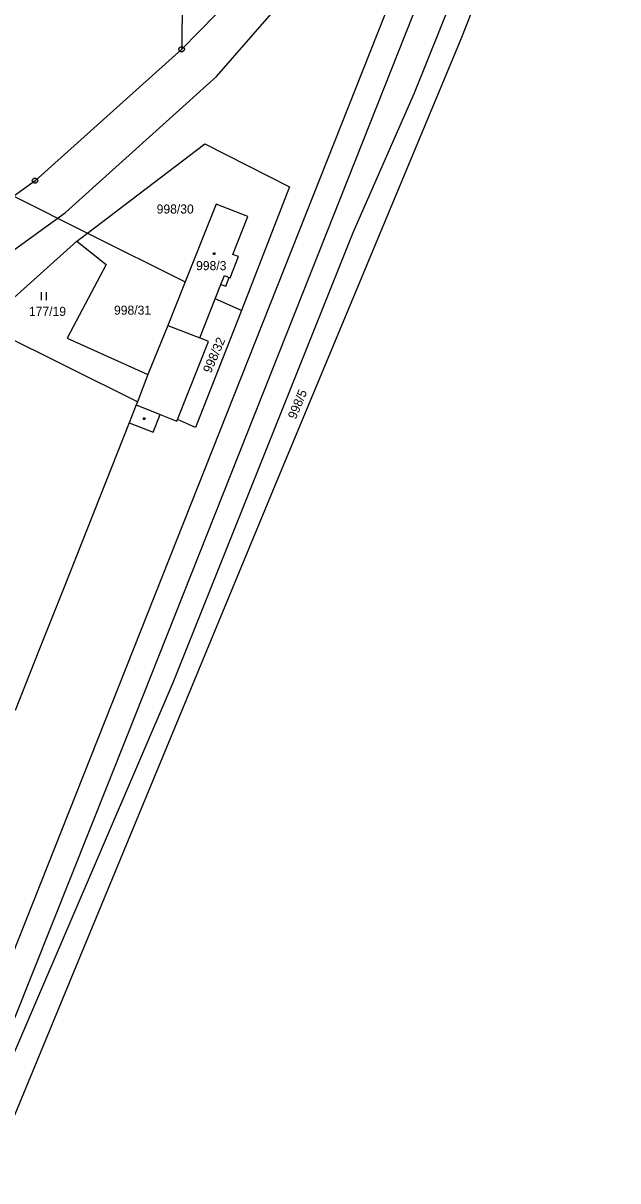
# Model space of a CAD drawing. Extents: x -755359 to -754474, y -1162585 to -1161655.
# Drawn here: x -754898.3 to -754786.7, y -1162361.4 to -1162144.3 of the extents above; entities that cross this region are included whole.
import ezdxf

# ---------------------------------------------------------------- set-up
doc = ezdxf.new("R2010")
doc.units = 0
for name, color, linetype in [('Vrstva 1', 7, 'Continuous'), ('Vrstva 11', 7, 'Continuous'), ('Vrstva 12', 7, 'Continuous'), ('Vrstva 2', 7, 'Continuous'), ('Vrstva 3', 7, 'Continuous'), ('Vrstva 4', 7, 'Continuous'), ('Vrstva 5', 7, 'Continuous'), ('Vrstva 6', 7, 'Continuous'), ('Vrstva 8', 7, 'Continuous')]:
    doc.layers.add(name, color=color, linetype=linetype)

msp = doc.modelspace()

# ---------------------------------------------------------------- linework, layer by layer
at = {"layer": 'Vrstva 1'}
for p, q in [((-754824.89, -1162157.4), (-754808.97, -1162117.64)), ((-754868.42, -1162135.23), (-754868.56, -1162149.23)), ((-754811.54, -1162135.54), (-754816.22, -1162147.35)), ((-754862.16, -1162142.69), (-754868.56, -1162149.23)), ((-754868.56, -1162149.23), (-754896.07, -1162173.88)), ((-754816.22, -1162147.35), (-754851.45, -1162231.96)), ((-754836.4, -1162183.6), (-754824.89, -1162157.4)), ((-754886.23, -1162183.69), (-754864.19, -1162166.97)), ((-754864.19, -1162166.97), (-754848.34, -1162175.05)), ((-754896.07, -1162173.88), (-754900.06, -1162176.77)), ((-754848.34, -1162175.05), (-754857.37, -1162198.21)), ((-754900.06, -1162176.77), (-754886.23, -1162183.69)), ((-754862.1, -1162178.26), (-754867.91, -1162192.86)), ((-754856.15, -1162180.61), (-754862.1, -1162178.26)), ((-754858.96, -1162187.7), (-754856.15, -1162180.61)), ((-754888.26, -1162185.23), (-754886.23, -1162183.69)), ((-754886.23, -1162183.69), (-754867.91, -1162192.86)), ((-754870.17, -1162267.96), (-754836.4, -1162183.6)), ((-754888.26, -1162185.23), (-754905.78, -1162201)), ((-754888.26, -1162185.23), (-754882.73, -1162189.61)), ((-754859.46, -1162192.12), (-754857.88, -1162188.11)), ((-754857.88, -1162188.11), (-754858.96, -1162187.7)), ((-754882.73, -1162189.61), (-754890.05, -1162203.42)), ((-754860.31, -1162193.68), (-754859.66, -1162192.04)), ((-754859.66, -1162192.04), (-754859.46, -1162192.12)), ((-754867.91, -1162192.86), (-754871.15, -1162201.02)), ((-754862.27, -1162196.01), (-754861.2, -1162193.33)), ((-754861.2, -1162193.33), (-754860.31, -1162193.68)), ((-754865.18, -1162203.36), (-754862.27, -1162196.01)), ((-754857.37, -1162198.21), (-754862.27, -1162196.01)), ((-754857.37, -1162198.21), (-754865.94, -1162220.19)), ((-754876.85, -1162215.37), (-754905.78, -1162201)), ((-754871.15, -1162201.02), (-754874.91, -1162210.24)), ((-754890.05, -1162203.42), (-754874.91, -1162210.24)), ((-754863.54, -1162204.02), (-754865.18, -1162203.36)), ((-754869.36, -1162218.68), (-754863.54, -1162204.02)), ((-754874.91, -1162210.24), (-754876.85, -1162215.37)), ((-754877.09, -1162215.93), (-754878.41, -1162219.27)), ((-754876.85, -1162215.37), (-754877.09, -1162215.93)), ((-754873.93, -1162221.05), (-754872.61, -1162217.71)), ((-754872.61, -1162217.71), (-754869.47, -1162218.96)), ((-754869.47, -1162218.96), (-754869.36, -1162218.68)), ((-754865.94, -1162220.19), (-754869.36, -1162218.68)), ((-754878.41, -1162219.27), (-754890.63, -1162250.1)), ((-754878.41, -1162219.27), (-754873.93, -1162221.05)), ((-754851.45, -1162231.96), (-754887.61, -1162319.28)), ((-754890.63, -1162250.1), (-754895.21, -1162261.65)), ((-754895.21, -1162261.65), (-754899.8, -1162273.21)), ((-754930.02, -1162407.36), (-754870.17, -1162267.96)), ((-754887.61, -1162319.28), (-754904.19, -1162359.38))]:
    msp.add_line(p, q, dxfattribs=at)
at = {"layer": 'Vrstva 11'}
for p, q in [((-754811.54, -1162135.54), (-754816.22, -1162147.35)), ((-754816.22, -1162147.35), (-754851.45, -1162231.96)), ((-754851.45, -1162231.96), (-754887.61, -1162319.28)), ((-754887.61, -1162319.28), (-754904.19, -1162359.38))]:
    msp.add_line(p, q, dxfattribs=at)
at = {"layer": 'Vrstva 12'}
for p, q in [((-754862.1, -1162178.26), (-754867.91, -1162192.86)), ((-754856.15, -1162180.61), (-754862.1, -1162178.26)), ((-754858.96, -1162187.7), (-754856.15, -1162180.61)), ((-754859.46, -1162192.12), (-754857.88, -1162188.11)), ((-754857.88, -1162188.11), (-754858.96, -1162187.7)), ((-754861.2, -1162193.33), (-754860.55, -1162191.69)), ((-754860.55, -1162191.69), (-754859.66, -1162192.04)), ((-754859.66, -1162192.04), (-754859.46, -1162192.12)), ((-754867.91, -1162192.86), (-754871.15, -1162201.02)), ((-754862.27, -1162196.01), (-754861.2, -1162193.33)), ((-754865.18, -1162203.36), (-754862.27, -1162196.01)), ((-754871.15, -1162201.02), (-754865.18, -1162203.36))]:
    msp.add_line(p, q, dxfattribs=at)
at = {"layer": 'Vrstva 3'}
for p, q in [((-754894.89, -1162194.76), (-754894.89, -1162196.26)), ((-754893.89, -1162196.26), (-754893.89, -1162194.76))]:
    msp.add_line(p, q, dxfattribs=at)
at = {"layer": 'Vrstva 4'}
for p, q in [((-754861.2, -1162193.33), (-754860.55, -1162191.69)), ((-754860.55, -1162191.69), (-754859.66, -1162192.04)), ((-754871.15, -1162201.02), (-754865.18, -1162203.36)), ((-754877.09, -1162215.93), (-754872.61, -1162217.71))]:
    msp.add_line(p, q, dxfattribs=at)
at = {"layer": 'Vrstva 5'}
for points in [[(-754862.4, -1162187.42), (-754862.31, -1162187.57), (-754862.4, -1162187.72), (-754862.58, -1162187.72), (-754862.67, -1162187.57), (-754862.58, -1162187.42)], [(-754875.49, -1162218.34), (-754875.4, -1162218.49), (-754875.49, -1162218.64), (-754875.67, -1162218.64), (-754875.76, -1162218.49), (-754875.67, -1162218.34)]]:
    msp.add_lwpolyline(points, close=True, dxfattribs=at)
at = {"layer": 'Vrstva 6'}
for p, q in [((-755000.46, -1162571.42), (-754786.74, -1162032.64)), ((-754811.99, -1162109.48), (-754841.46, -1162183.87)), ((-754862.02, -1162154.33), (-754839.32, -1162128.13)), ((-754890.36, -1162179.87), (-754862.02, -1162154.33)), ((-754910.99, -1162194.73), (-754890.36, -1162179.87)), ((-754841.46, -1162183.87), (-754878.79, -1162277.91)), ((-754878.79, -1162277.91), (-754899.91, -1162330.95))]:
    msp.add_line(p, q, dxfattribs=at)
at = {"layer": 'Vrstva 8'}
for p, q in [((-754868.68, -1162149.23), (-754868.44, -1162149.23)), ((-754896.19, -1162173.88), (-754895.95, -1162173.88))]:
    msp.add_line(p, q, dxfattribs=at)
for points in [[(-754868.41, -1162148.75), (-754868.16, -1162148.93), (-754868.06, -1162149.22), (-754868.16, -1162149.51), (-754868.41, -1162149.69), (-754868.72, -1162149.69), (-754868.97, -1162149.51), (-754869.07, -1162149.22), (-754868.97, -1162148.93), (-754868.72, -1162148.75)], [(-754895.92, -1162173.4), (-754895.67, -1162173.58), (-754895.57, -1162173.87), (-754895.67, -1162174.16), (-754895.92, -1162174.34), (-754896.23, -1162174.34), (-754896.48, -1162174.16), (-754896.58, -1162173.87), (-754896.48, -1162173.58), (-754896.23, -1162173.4)]]:
    msp.add_lwpolyline(points, close=True, dxfattribs=at)

# ---------------------------------------------------------------- texts
at = {"layer": 'Vrstva 2'}
for s, p in [('998/30', (-754873.253, -1162180.04)), ('998/3', (-754865.857, -1162190.66)), ('177/19', (-754897.217, -1162199.23)), ('998/31', (-754881.253, -1162199.01))]:
    msp.add_text(s, height=1.7, dxfattribs=at).set_placement(p)
for s, rotation, p in [('998/32', 66.57769, (-754863.096, -1162210.102)), ('998/5', 67.49443, (-754847.149, -1162218.741))]:
    msp.add_text(s, height=1.7, rotation=rotation, dxfattribs=at).set_placement(p)

doc.saveas('drawing.dxf')
